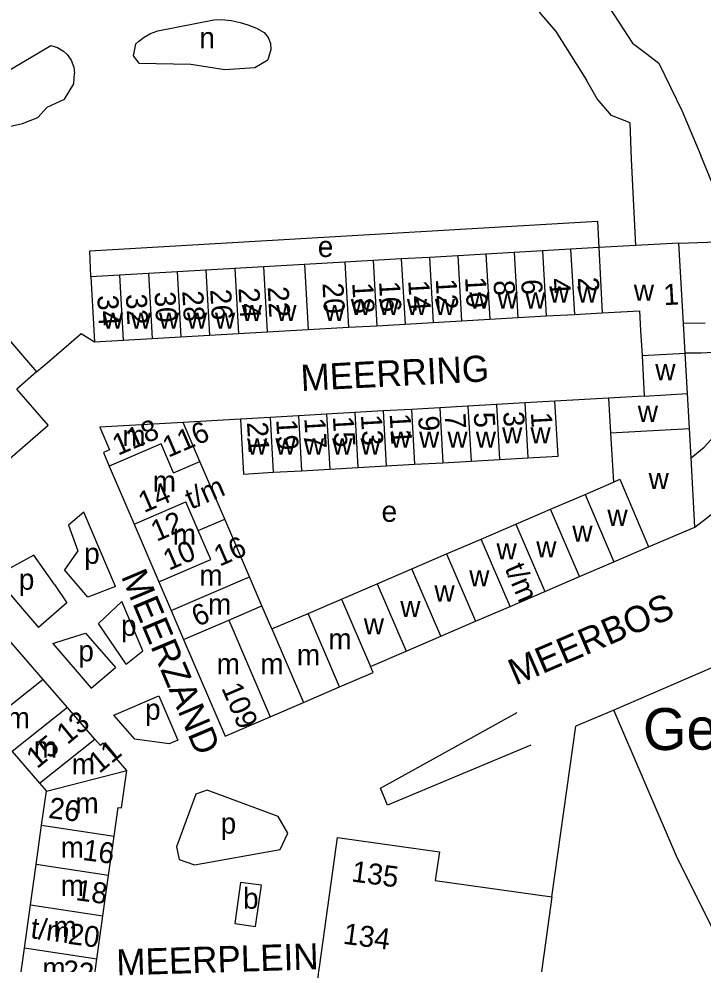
# Model space of a CAD drawing. Extents: x 155696 to 157795, y 382328 to 384028.
# Drawn here: x 156506.7 to 156637.4, y 383706.4 to 383886.8 of the extents above; entities that cross this region are included whole.
import ezdxf

# ---------------------------------------------------------------- set-up
doc = ezdxf.new("R2010")
doc.units = 0
for name, color, linetype in [('BLT_Basislijn', 7, 'Continuous'), ('BLT_Bebouwing', 7, 'Continuous'), ('BLT_Bebouwing_beschrifting', 7, 'Continuous'), ('BLT_Centroide', 7, 'Continuous'), ('BLT_Huisnummer', 7, 'Continuous'), ('BLT_Huisnummer_ tussenligend', 7, 'Continuous'), ('BLT_Huisnummer_reeks', 7, 'Continuous'), ('BLT_Onderverdeling_panden', 7, 'Continuous'), ('BLT_Straatnaam', 7, 'Continuous'), ('BLT_Vlakafsluiter', 7, 'Continuous')]:
    doc.layers.add(name, color=color, linetype=linetype)

msp = doc.modelspace()

# ---------------------------------------------------------------- linework, layer by layer
at = {"layer": 'BLT_Basislijn'}
for p, q in [((156637.77, 383828.73), (156633.62, 383828.7)), ((156637.01, 383823.01), (156633.95, 383823.02)), ((156619.31, 383814.42), (156609.07, 383813.84)), ((156548.99, 383810.42), (156538.06, 383809.8)), ((156519.85, 383776.43), (156515.42, 383781.67)), ((156525.12, 383778.48), (156519.85, 383776.43)), ((156515.3, 383768.27), (156519.42, 383769.58)), ((156519.42, 383769.58), (156525.13, 383763)), ((156513.13, 383767.58), (156515.3, 383768.27)), ((156620.33, 383754.86), (156613.07, 383751.81)), ((156608.49, 383719.18), (156613.07, 383751.81))]:
    msp.add_line(p, q, dxfattribs=at)
for points in [[(156606.02, 383907.63), (156615.79, 383894.68), (156623.9, 383882.19)], [(156528.93, 383882), (156529.55, 383882.55), (156530.64, 383883.35), (156531.81, 383884.02), (156533.2, 383884.53), (156543.92, 383886.67), (156545.38, 383886.69), (156547.25, 383886.5), (156548.95, 383886.12), (156550.41, 383885.72), (156552.04, 383885.05), (156553.55, 383884.21), (156554.32, 383883.3), (156554.76, 383882.13), (156554.78, 383880.96), (156554.5, 383879.92), (156554.25, 383879.05)], [(156606.1, 383888.09), (156609.26, 383884.46), (156615.11, 383875.13)], [(156487.92, 383865.39), (156487.42, 383866.24), (156487.19, 383867.12), (156487.22, 383868.14), (156487.52, 383869.08), (156488.16, 383869.97), (156489.83, 383871.31), (156491.86, 383872.51), (156493.95, 383873.39), (156495.92, 383873.89), (156497.15, 383873.67), (156498.33, 383873.67), (156499.74, 383873.99), (156500.89, 383874.54), (156501.78, 383875.25), (156512.76, 383881.74), (156514.08, 383881.37), (156515.21, 383880.7), (156515.89, 383880.01), (156516.65, 383878.96), (156517.18, 383877.64), (156517.3, 383876.48)], [(156528.93, 383882), (156528.51, 383879.78), (156529.58, 383878.38), (156539.52, 383878.22), (156546.01, 383877.15), (156551.76, 383877.56), (156554.25, 383879.05)], [(156623.9, 383882.19), (156626.73, 383880.11), (156628.9, 383878.37), (156633.42, 383869.21), (156636.98, 383860.73)], [(156487.92, 383865.39), (156490.3, 383863.05), (156493.41, 383862.39), (156501.31, 383865.53), (156507.39, 383866.87), (156510.29, 383867.99), (156512.06, 383869.97), (156515.41, 383871.54), (156517.18, 383874.41), (156517.3, 383876.48)], [(156623.68, 383860.04), (156623.48, 383867.02), (156619.88, 383868.36), (156617.18, 383871.57), (156615.11, 383875.13)], [(156459.68, 383861.63), (156461.29, 383860.8), (156466.2, 383858.15), (156471.98, 383854.64), (156481.11, 383848.19), (156489.77, 383841.09), (156500.02, 383831.03), (156510.07, 383819.43)], [(156624.55, 383843.56), (156623.68, 383860.04)], [(156643.73, 383844.42), (156636.98, 383860.73)], [(156520.42, 383837.61), (156520.21, 383842.58), (156617.21, 383848.24), (156617.47, 383843.17)], [(156632.77, 383844.01), (156643.73, 383844.42)], [(156512.45, 383821.48), (156518.56, 383826.76), (156521.1, 383825.18)], [(156635.09, 383803.03), (156637.62, 383805.08), (156641.42, 383809.29), (156645.85, 383816.95), (156647.27, 383820.91), (156646.79, 383822.73), (156645.16, 383823.46), (156637.01, 383823.01)], [(156510.07, 383819.43), (156512.45, 383821.48)], [(156635.84, 383789.82), (156640.27, 383793.23), (156645.47, 383798.28), (156647.51, 383801.34), (156652.24, 383808.26), (156656, 383815.65), (156658.1, 383822.4)], [(156489.33, 383786.04), (156489.95, 383786.58), (156489.22, 383787.43), (156496.92, 383794.08), (156496, 383795.18), (156512.27, 383809.26), (156506.28, 383816.17)], [(156525.12, 383778.48), (156519.07, 383792.67), (156516.13, 383790.19), (156517.91, 383785.26), (156515.42, 383781.67)], [(156513.47, 383778.84), (156509.53, 383784.43), (156502, 383780.35), (156510.42, 383770.66)], [(156513.47, 383778.84), (156515.84, 383775.34), (156510.42, 383770.66)], [(156527.14, 383763.65), (156521.87, 383771.38), (156526.32, 383775.6)], [(156527.14, 383763.65), (156530.38, 383766.15), (156526.32, 383775.6)], [(156513.13, 383767.58), (156520.51, 383759.02), (156525.13, 383763)], [(156575.75, 383739.95), (156601.87, 383754.4)], [(156604.48, 383748.19), (156577.12, 383736.68), (156575.75, 383739.95)]]:
    msp.add_lwpolyline(points, dxfattribs=at)
for points in [[(156533.44, 383757.58), (156537.06, 383749.12), (156535.39, 383748.43), (156528.81, 383749.34), (156524.84, 383753.88)], [(156540.5, 383738.8), (156536.76, 383728.74), (156537.32, 383726.32), (156540.21, 383725.33), (156556.57, 383728.22), (156558.08, 383731.39), (156556.21, 383734.56), (156542.62, 383739.56)]]:
    msp.add_lwpolyline(points, close=True, dxfattribs=at)
at = {"layer": 'BLT_Bebouwing'}
for p, q in [((156617.46, 383843.17), (156612.07, 383842.86)), ((156632.77, 383844.01), (156624.55, 383843.56)), ((156633.62, 383828.7), (156632.77, 383844.01)), ((156585.12, 383841.31), (156579.73, 383841.01)), ((156590.51, 383841.62), (156585.12, 383841.31)), ((156595.9, 383841.93), (156590.51, 383841.62)), ((156601.29, 383842.24), (156595.9, 383841.93)), ((156606.68, 383842.55), (156601.29, 383842.24)), ((156612.07, 383842.86), (156606.68, 383842.55)), ((156553.41, 383839.5), (156547.91, 383839.18)), ((156561.24, 383839.95), (156553.41, 383839.5)), ((156568.95, 383840.39), (156561.24, 383839.95)), ((156574.34, 383840.7), (156568.95, 383840.39)), ((156579.73, 383841.01), (156574.34, 383840.7)), ((156531.42, 383838.24), (156525.92, 383837.93)), ((156536.92, 383838.56), (156531.42, 383838.24)), ((156542.41, 383838.87), (156536.92, 383838.56)), ((156547.91, 383839.18), (156542.41, 383838.87)), ((156607.4, 383830.11), (156612.79, 383830.41)), ((156612.79, 383830.41), (156618.13, 383830.72)), ((156580.44, 383828.57), (156585.83, 383828.88)), ((156585.83, 383828.88), (156591.22, 383829.18)), ((156591.22, 383829.18), (156596.62, 383829.49)), ((156596.62, 383829.49), (156602.01, 383829.8)), ((156602.01, 383829.8), (156607.4, 383830.11)), ((156633.95, 383823.02), (156633.62, 383828.7)), ((156548.62, 383826.75), (156554.12, 383827.07)), ((156554.12, 383827.07), (156561.95, 383827.51)), ((156561.95, 383827.51), (156569.66, 383827.95)), ((156569.66, 383827.95), (156575.05, 383828.26)), ((156575.05, 383828.26), (156580.44, 383828.57)), ((156526.62, 383825.49), (156532.12, 383825.81)), ((156532.12, 383825.81), (156537.62, 383826.12)), ((156537.62, 383826.12), (156543.12, 383826.44)), ((156543.12, 383826.44), (156548.62, 383826.75)), ((156634.39, 383815.28), (156633.95, 383823.02)), ((156626.16, 383814.81), (156619.31, 383814.42)), ((156587.07, 383812.59), (156581.69, 383812.28)), ((156592.46, 383812.89), (156587.07, 383812.59)), ((156597.9, 383813.2), (156592.46, 383812.89)), ((156603.32, 383813.51), (156597.9, 383813.2)), ((156609.07, 383813.84), (156603.32, 383813.51)), ((156554.66, 383810.74), (156548.99, 383810.42)), ((156560.07, 383811.05), (156554.66, 383810.74)), ((156565.46, 383811.36), (156560.07, 383811.05)), ((156570.87, 383811.67), (156565.46, 383811.36)), ((156576.27, 383811.97), (156570.87, 383811.67)), ((156581.69, 383812.28), (156576.27, 383811.97)), ((156619.72, 383807.79), (156620.3, 383798.39)), ((156603.91, 383803.03), (156609.67, 383803.36)), ((156546.01, 383791.31), (156541.27, 383802.34)), ((156576.87, 383801.49), (156582.28, 383801.8)), ((156582.28, 383801.8), (156587.66, 383802.1)), ((156587.66, 383802.1), (156593.06, 383802.41)), ((156593.06, 383802.41), (156598.49, 383802.72)), ((156598.49, 383802.72), (156603.91, 383803.03)), ((156635.84, 383789.82), (156635.09, 383803.03)), ((156523.93, 383801.41), (156528.67, 383790.39)), ((156555.26, 383800.26), (156560.67, 383800.57)), ((156560.67, 383800.57), (156566.06, 383800.87)), ((156566.06, 383800.87), (156571.46, 383801.18)), ((156571.46, 383801.18), (156576.87, 383801.49)), ((156614.83, 383796.04), (156620.3, 383798.39)), ((156608.22, 383793.2), (156614.83, 383796.04)), ((156601.6, 383790.36), (156608.22, 383793.2)), ((156550.75, 383780.29), (156546.01, 383791.31)), ((156528.67, 383790.39), (156533.41, 383779.37)), ((156594.98, 383787.52), (156601.6, 383790.36)), ((156626.98, 383786.02), (156635.84, 383789.82)), ((156588.37, 383784.68), (156594.98, 383787.52)), ((156620.36, 383783.18), (156626.98, 383786.02)), ((156581.75, 383781.84), (156588.37, 383784.68)), ((156575.14, 383779), (156581.75, 383781.84)), ((156613.75, 383780.34), (156620.36, 383783.18)), ((156553.12, 383774.78), (156550.75, 383780.29)), ((156607.13, 383777.5), (156613.75, 383780.34)), ((156680.48, 383780.83), (156620.33, 383754.86)), ((156533.41, 383779.37), (156535.78, 383773.85)), ((156568.3, 383776.06), (156575.14, 383779)), ((156600.51, 383774.66), (156607.13, 383777.5)), ((156555.02, 383770.36), (156553.12, 383774.78)), ((156561.91, 383773.32), (156568.3, 383776.06)), ((156593.9, 383771.82), (156600.51, 383774.66)), ((156535.78, 383773.85), (156538.15, 383768.34)), ((156555.02, 383770.36), (156561.91, 383773.32)), ((156587.28, 383768.98), (156593.9, 383771.82)), ((156511.32, 383760.71), (156504.74, 383768.29)), ((156580.67, 383766.14), (156587.28, 383768.98)), ((156515.96, 383755.37), (156511.32, 383760.71)), ((156561.06, 383756.32), (156567.94, 383759.28)), ((156521.21, 383749.32), (156515.96, 383755.37)), ((156554.71, 383753.59), (156561.06, 383756.32)), ((156505.38, 383746.96), (156510.63, 383740.91)), ((156509.97, 383725.4), (156511.02, 383732.9)), ((156523.82, 383723.31), (156524.86, 383730.81)), ((156508.9, 383717.69), (156509.97, 383725.4)), ((156522.74, 383715.6), (156523.82, 383723.31)), ((156507.74, 383709.39), (156508.9, 383717.69)), ((156521.59, 383707.29), (156522.74, 383715.6)), ((156506.8, 383702.61), (156507.74, 383709.39)), ((156520.64, 383700.52), (156521.59, 383707.29))]:
    msp.add_line(p, q, dxfattribs=at)
for points in [[(156624.55, 383843.56), (156617.47, 383843.17)], [(156525.92, 383837.93), (156520.42, 383837.61)], [(156520.42, 383837.61), (156521.1, 383825.18)], [(156618.13, 383830.72), (156625.23, 383831.12), (156625.45, 383827.35)], [(156625.45, 383827.35), (156625.72, 383822.55)], [(156521.1, 383825.18), (156526.62, 383825.49)], [(156625.72, 383822.55), (156626.16, 383814.81)], [(156619.31, 383814.42), (156619.72, 383807.79)], [(156634.77, 383808.64), (156634.39, 383815.28)], [(156609.67, 383803.36), (156609.07, 383813.84)], [(156538.06, 383809.8), (156522.11, 383808.89), (156524, 383804.53), (156522.81, 383804.02), (156523.93, 383801.41)], [(156541.27, 383802.34), (156538.06, 383809.8)], [(156548.99, 383810.42), (156549.59, 383799.93), (156555.26, 383800.26)], [(156635.09, 383803.03), (156634.77, 383808.64)], [(156538.15, 383768.34), (156546.1, 383749.87), (156554.71, 383753.59)], [(156573.83, 383763.2), (156580.67, 383766.14)], [(156567.94, 383759.28), (156574.33, 383762.04), (156573.83, 383763.2)], [(156652.41, 383686.74), (156632.48, 383726.5), (156620.33, 383754.86)], [(156527.29, 383743.32), (156522.76, 383748.57), (156522.24, 383748.13), (156521.21, 383749.32)], [(156524.86, 383730.81), (156525.62, 383736.26), (156526.28, 383736.17), (156527.29, 383743.32)], [(156510.63, 383740.91), (156511.93, 383739.41)], [(156511.02, 383732.9), (156511.93, 383739.41)], [(156554.46, 383636.53), (156567.52, 383730.54)], [(156567.52, 383730.54), (156587.01, 383727.82), (156586.22, 383722.3), (156608.49, 383719.18)], [(156608.49, 383719.18), (156596.24, 383630.68), (156581.12, 383632.79)]]:
    msp.add_lwpolyline(points, dxfattribs=at)
msp.add_lwpolyline([(156549.01, 383721.97), (156547.91, 383714.09), (156551.91, 383713.53), (156553.01, 383721.41)], close=True, dxfattribs=at)
at = {"layer": 'BLT_Onderverdeling_panden'}
for p, q in [((156585.12, 383841.31), (156585.83, 383828.88)), ((156590.51, 383841.62), (156591.22, 383829.18)), ((156595.9, 383841.93), (156596.62, 383829.49)), ((156601.29, 383842.24), (156602.01, 383829.8)), ((156606.68, 383842.55), (156607.4, 383830.11)), ((156612.07, 383842.86), (156612.79, 383830.41)), ((156553.41, 383839.5), (156554.12, 383827.07)), ((156561.24, 383839.95), (156561.95, 383827.51)), ((156568.95, 383840.39), (156569.66, 383827.95)), ((156574.34, 383840.7), (156575.05, 383828.26)), ((156579.73, 383841.01), (156580.44, 383828.57)), ((156525.92, 383837.93), (156526.62, 383825.49)), ((156531.42, 383838.24), (156532.12, 383825.81)), ((156536.92, 383838.56), (156537.62, 383826.12)), ((156542.41, 383838.87), (156543.12, 383826.44)), ((156547.91, 383839.18), (156548.62, 383826.75)), ((156625.72, 383822.55), (156633.95, 383823.02)), ((156626.16, 383814.81), (156634.39, 383815.28)), ((156587.07, 383812.59), (156587.66, 383802.1)), ((156592.46, 383812.89), (156593.06, 383802.41)), ((156597.9, 383813.2), (156598.49, 383802.72)), ((156603.32, 383813.51), (156603.91, 383803.03)), ((156554.66, 383810.74), (156555.26, 383800.26)), ((156560.07, 383811.05), (156560.67, 383800.57)), ((156565.46, 383811.36), (156566.06, 383800.87)), ((156570.87, 383811.67), (156571.46, 383801.18)), ((156576.27, 383811.97), (156576.87, 383801.49)), ((156581.69, 383812.28), (156582.28, 383801.8)), ((156619.72, 383807.79), (156634.77, 383808.64)), ((156536.22, 383800.16), (156541.27, 383802.34)), ((156528.67, 383790.39), (156538.59, 383794.65)), ((156540.95, 383789.14), (156538.59, 383794.65)), ((156614.83, 383796.04), (156620.36, 383783.18)), ((156613.75, 383780.34), (156608.22, 383793.2)), ((156540.95, 383789.14), (156546.01, 383791.31)), ((156601.6, 383790.36), (156607.13, 383777.5)), ((156600.51, 383774.66), (156594.98, 383787.52)), ((156588.37, 383784.68), (156593.9, 383771.82)), ((156587.28, 383768.98), (156581.75, 383781.84)), ((156535.78, 383773.85), (156550.75, 383780.29)), ((156575.14, 383779), (156580.67, 383766.14)), ((156546.78, 383772.05), (156553.12, 383774.78)), ((156568.3, 383776.06), (156573.83, 383763.2)), ((156567.94, 383759.28), (156561.91, 383773.32)), ((156538.15, 383768.34), (156546.78, 383772.05)), ((156546.78, 383772.05), (156554.71, 383753.59)), ((156555.02, 383770.36), (156561.06, 383756.32)), ((156511.32, 383760.71), (156500.75, 383752.3)), ((156515.96, 383755.37), (156505.38, 383746.96)), ((156510.63, 383740.91), (156521.21, 383749.32)), ((156511.93, 383739.41), (156527.29, 383743.32)), ((156511.02, 383732.9), (156524.86, 383730.81)), ((156523.82, 383723.31), (156509.97, 383725.4)), ((156508.9, 383717.69), (156522.74, 383715.6)), ((156521.59, 383707.29), (156507.74, 383709.39))]:
    msp.add_line(p, q, dxfattribs=at)
for points in [[(156617.47, 383843.17), (156618.13, 383830.72)], [(156536.22, 383800.16), (156533.85, 383805.68), (156523.93, 383801.41)], [(156620.3, 383798.39), (156621.46, 383798.93), (156626.98, 383786.02)], [(156533.41, 383779.37), (156543.32, 383783.63), (156540.95, 383789.14)]]:
    msp.add_lwpolyline(points, dxfattribs=at)
at = {"layer": 'BLT_Vlakafsluiter'}
msp.add_line((156510.07, 383819.43), (156506.28, 383816.17), dxfattribs=at)

# ---------------------------------------------------------------- texts
at = {"layer": 'BLT_Bebouwing_beschrifting'}
msp.add_text('Gemeenschapshuis', height=8, rotation=0.5505, dxfattribs=at).set_placement((156625.93, 383747.2))
at = {"layer": 'BLT_Centroide'}
for s, p in [('n', (156541.15, 383881.24)), ('e', (156563.78, 383841.37)), ('w', (156624.15, 383833.01)), ('w', (156592.73, 383831.53)), ('w', (156598.09, 383831.53)), ('w', (156603.44, 383831.53)), ('w', (156607.99, 383832.67)), ('w', (156613.34, 383832.67)), ('w', (156570.08, 383830.28)), ('w', (156575.43, 383830.28)), ('w', (156580.79, 383830.28)), ('w', (156586.14, 383830.28)), ('w', (156522.72, 383827.66)), ('w', (156528.07, 383827.66)), ('w', (156533.43, 383827.66)), ('w', (156538.78, 383827.66)), ('w', (156544.13, 383827.66)), ('w', (156549.25, 383829.14)), ('w', (156555.85, 383829.14)), ('w', (156565.07, 383829.14)), ('w', (156628.25, 383817.85)), ('w', (156624.91, 383809.89)), ('w', (156598.99, 383805.77)), ('w', (156604.41, 383805.77)), ('m', (156526.44, 383805.28)), ('w', (156577.71, 383804.98)), ('w', (156583.13, 383804.98)), ('w', (156588.55, 383804.98)), ('w', (156593.97, 383804.98)), ('w', (156550.26, 383803.65)), ('w', (156555.68, 383803.65)), ('w', (156561.1, 383803.65)), ('w', (156566.52, 383803.65)), ('w', (156571.94, 383803.65)), ('w', (156626.98, 383797.06)), ('m', (156532.24, 383796.56)), ('e', (156575.96, 383790.81)), ('w', (156619.11, 383790.04)), ('m', (156536.06, 383786.42)), ('w', (156612.41, 383787)), ('p', (156519.15, 383782.79)), ('w', (156597.93, 383783.63)), ('w', (156605.52, 383784.02)), ('m', (156541.15, 383778.63)), ('p', (156506.66, 383777.84)), ('w', (156592.71, 383778.5)), ('w', (156586.06, 383775.59)), ('m', (156542.8, 383773.1)), ('w', (156579.54, 383772.63)), ('p', (156526.18, 383769.03)), ('w', (156572.57, 383769.33)), ('m', (156565.79, 383766.44)), ('p', (156518.03, 383764.18)), ('m', (156559.77, 383763.43)), ('m', (156544.45, 383761.69)), ('m', (156552.79, 383761.69)), ('p', (156530.78, 383753.02)), ('m', (156504.32, 383751.4)), ('m', (156509.52, 383745.8)), ('m', (156516.78, 383742.58)), ('m', (156517.47, 383735.12)), ('p', (156545.22, 383731.27)), ('m', (156514.66, 383726.68)), ('m', (156514.66, 383719.39)), ('b', (156549.5, 383716.92)), ('m', (156513.28, 383711.53)), ('m', (156511.15, 383703.66))]:
    msp.add_text(s, height=4, dxfattribs=at).set_placement(p)
at = {"layer": 'BLT_Huisnummer'}
for s, p in [('18', (156570.35, 383836.4)), ('14', (156581.05, 383836.88)), ('10', (156591.91, 383837.5)), ('6', (156602.62, 383837.04)), ('2', (156613.44, 383837.45)), ('30', (156532.57, 383834.68)), ('26', (156543.22, 383835.15)), ('22', (156554.2, 383835.65)), ('34', (156521.64, 383834.03)), ('13', (156572.01, 383811.2)), ('9', (156582.95, 383810.97)), ('5', (156593.56, 383811.65)), ('1', (156604.48, 383811.67)), ('21', (156550.24, 383809.81)), ('17', (156561.2, 383810.59))]:
    msp.add_text(s, height=4, rotation=273.26, dxfattribs=at).set_placement(p)
at = {"layer": 'BLT_Huisnummer_ tussenligend'}
for s, p in [('20', (156564.66, 383836.37)), ('16', (156575.47, 383836.69)), ('12', (156586.3, 383837.15)), ('8', (156597.34, 383836.85)), ('4', (156607.97, 383837.23)), ('32', (156527.09, 383834.25)), ('28', (156537.88, 383834.86)), ('24', (156548.62, 383835.43)), ('11', (156577.5, 383811.42)), ('7', (156587.99, 383811.42)), ('3', (156599.19, 383811.82)), ('19', (156555.83, 383810.3)), ('15', (156566.65, 383810.88))]:
    msp.add_text(s, height=4, rotation=273.26, dxfattribs=at).set_placement(p)
at = {"layer": 'BLT_Huisnummer_reeks'}
for s, rotation, p in [('1', 3.26, (156629.91, 383832.16)), ('118', 23.26, (156525.61, 383803.4)), ('116', 23.26, (156535.22, 383803.02)), ('14', 23.26, (156530.58, 383792.47)), ('t/m', 23.26, (156539.56, 383793.11)), ('12', 23.26, (156532.97, 383786.97)), ('10', 23.26, (156535.32, 383781.45)), ('16', 23.26, (156545.02, 383782.23)), ('t/m', 293.26, (156599.43, 383781.93)), ('6', 23.26, (156540.75, 383770.72)), ('109', 293.26, (156545.31, 383759.09)), ('13', 39.4756, (156515.94, 383748.15)), ('15', 39.4756, (156510.15, 383743.54)), ('11', 39.4756, (156522.04, 383742.64)), ('26', 352.3925, (156512.19, 383734.3)), ('16', 352.3925, (156518.72, 383726.26)), ('135', 352.3925, (156570.07, 383722.16)), ('18', 352.3925, (156517.39, 383718.59)), ('t/m', 352.3925, (156508.77, 383711.33)), ('20', 352.3925, (156515.92, 383710.26)), ('134', 352.3925, (156568.47, 383710.27)), ('22', 352.3925, (156514.79, 383703.26))]:
    msp.add_text(s, height=4, rotation=rotation, dxfattribs=at).set_placement(p)
at = {"layer": 'BLT_Straatnaam'}
for s, rotation, p in [('MEERRING', 3.012, (156560.63, 383815.77)), ('MEERZAND', 292.8773, (156526.13, 383780.42)), ('MEERBOS', 23.3306, (156601.57, 383759.52)), ('MEERPLEIN', 1.7798, (156525.37, 383704.18))]:
    msp.add_text(s, height=5, rotation=rotation, dxfattribs=at).set_placement(p)

doc.saveas('drawing.dxf')
